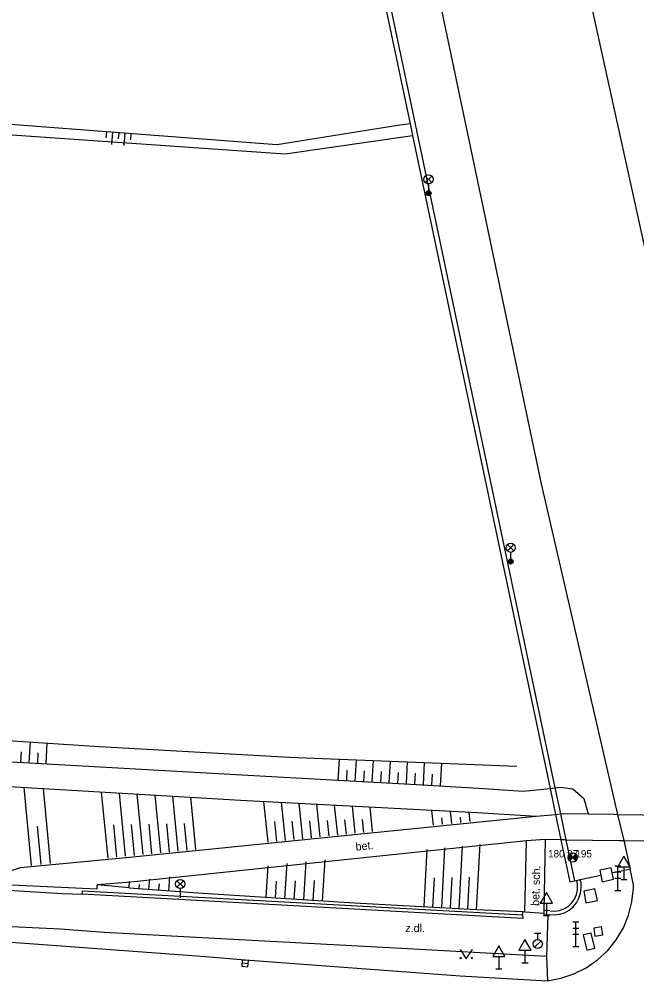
# Model space of a CAD drawing. Extents: x -538441 to -536770, y -1181008 to -1179809.
# Drawn here: x -537834.9 to -537784.8, y -1180620 to -1180541.9 of the extents above; entities that cross this region are included whole.
import ezdxf

# ---------------------------------------------------------------- set-up
doc = ezdxf.new("R2010")
doc.units = 0
for name, color, linetype in [('Vrstva 10', 7, 'Continuous'), ('Vrstva 11', 7, 'Continuous'), ('Vrstva 14', 7, 'Continuous'), ('Vrstva 15', 7, 'Continuous'), ('Vrstva 17', 7, 'Continuous'), ('Vrstva 18', 7, 'Continuous'), ('Vrstva 22', 7, 'Continuous'), ('Vrstva 27', 7, 'Continuous'), ('Vrstva 28', 7, 'Continuous'), ('Vrstva 33', 7, 'Continuous'), ('Vrstva 34', 7, 'Continuous'), ('Vrstva 36', 7, 'Continuous'), ('Vrstva 40', 7, 'Continuous'), ('Vrstva 7', 7, 'Continuous')]:
    doc.layers.add(name, color=color, linetype=linetype)

msp = doc.modelspace()

# ---------------------------------------------------------------- linework, layer by layer
at = {"layer": 'Vrstva 10'}
for p, q in [((-537782.938, -1180565.756), (-537790.569, -1180530.964)), ((-537800.99, -1180539.42), (-537792.522, -1180579.638)), ((-537836.53, -1180602.14), (-537816.83, -1180603.26)), ((-537836.67, -1180604.15), (-537816.94, -1180605.31)), ((-537802.65, -1180604.04), (-537797.61, -1180604.34)), ((-537816.94, -1180605.31), (-537797.68, -1180606.33)), ((-537789.05, -1180605.19), (-537788.695, -1180606.438)), ((-537797.68, -1180606.33), (-537792.93, -1180606.63)), ((-537785.02, -1180612.192), (-537785.28, -1180610.905)), ((-537791.83, -1180614.314), (-537792.294, -1180614.271)), ((-537845.022, -1180616.127), (-537830.791, -1180617.208)), ((-537830.791, -1180617.208), (-537819.78, -1180618.02)), ((-537819.78, -1180618.02), (-537816.56, -1180618.29)), ((-537816.56, -1180618.29), (-537799.11, -1180619.59)), ((-537799.11, -1180619.59), (-537792.017, -1180619.988))]:
    msp.add_line(p, q, dxfattribs=at)
for points in [[(-537792.522, -1180579.638), (-537786.307, -1180606.472)], [(-537816.83, -1180603.26), (-537809.009, -1180603.69)], [(-537809.009, -1180603.69), (-537802.65, -1180604.04)], [(-537797.61, -1180604.34), (-537793.99, -1180604.58), (-537791.8, -1180604.359), (-537791.4, -1180604.319), (-537790.92, -1180604.27), (-537789.96, -1180604.41), (-537789.05, -1180605.19)], [(-537786.307, -1180606.472), (-537785.814, -1180608.6), (-537785.28, -1180610.905)], [(-537791.878, -1180614.61), (-537791.454, -1180614.638), (-537791.033, -1180614.587), (-537790.629, -1180614.458), (-537790.256, -1180614.255), (-537789.927, -1180613.986), (-537789.655, -1180613.66), (-537789.449, -1180613.289), (-537789.315, -1180612.886), (-537789.26, -1180612.465), (-537789.284, -1180612.041), (-537789.341, -1180611.776)], [(-537791.83, -1180614.314), (-537791.435, -1180614.338), (-537791.044, -1180614.282), (-537790.672, -1180614.148), (-537790.334, -1180613.943), (-537790.045, -1180613.673), (-537789.816, -1180613.352), (-537789.655, -1180612.99), (-537789.571, -1180612.604), (-537789.566, -1180612.209), (-537789.633, -1180611.839)], [(-537790.198, -1180611.962), (-537789.807, -1180611.877), (-537789.633, -1180611.839), (-537789.341, -1180611.776)], [(-537785.418, -1180614.664), (-537785.143, -1180613.579), (-537785.025, -1180612.466), (-537785.02, -1180612.192)], [(-537792.017, -1180619.988), (-537790.916, -1180619.789), (-537789.854, -1180619.435), (-537788.854, -1180618.934), (-537787.935, -1180618.295), (-537787.117, -1180617.532), (-537786.415, -1180616.661), (-537785.845, -1180615.698), (-537785.418, -1180614.664)]]:
    msp.add_lwpolyline(points, dxfattribs=at)
at = {"layer": 'Vrstva 11'}
for p, q in [((-537826.23, -1180609.98), (-537792.93, -1180606.63)), ((-537792.93, -1180606.63), (-537791.354, -1180606.477)), ((-537793.7, -1180608.63), (-537825.85, -1180611.97)), ((-537793.843, -1180614.38), (-537793.7, -1180608.63)), ((-537790.512, -1180608.534), (-537790.922, -1180608.528)), ((-537834.82, -1180610.79), (-537826.23, -1180609.98)), ((-537789.341, -1180611.776), (-537787.667, -1180611.413)), ((-537786.822, -1180610.81), (-537787.75, -1180610.995)), ((-537786.742, -1180611.213), (-537785.28, -1180610.905)), ((-537828.62, -1180612.56), (-537837.76, -1180612.13)), ((-537787.56, -1180611.949), (-537786.636, -1180611.741)), ((-537837.92, -1180612.49), (-537831.44, -1180612.91)), ((-537831.44, -1180612.91), (-537829.81, -1180612.96)), ((-537829.81, -1180612.96), (-537829.79, -1180612.67)), ((-537794.01, -1180614.93), (-537829.81, -1180612.96)), ((-537788.15, -1180612.53), (-537789.055, -1180612.71)), ((-537789.055, -1180612.71), (-537788.879, -1180613.653)), ((-537787.934, -1180613.464), (-537788.15, -1180612.53)), ((-537788.879, -1180613.653), (-537787.934, -1180613.464)), ((-537794.03, -1180614.62), (-537794.01, -1180614.93)), ((-537791.99, -1180614.62), (-537792.08, -1180618.02)), ((-537831.6, -1180615.8), (-537838.11, -1180615.49)), ((-537828.03, -1180616.08), (-537831.6, -1180615.8)), ((-537818.06, -1180616.62), (-537828.03, -1180616.08)), ((-537787.616, -1180615.603), (-537788.251, -1180615.717)), ((-537788.251, -1180615.717), (-537788.167, -1180616.376)), ((-537787.499, -1180616.256), (-537787.616, -1180615.603)), ((-537804.84, -1180617.32), (-537818.06, -1180616.62)), ((-537788.458, -1180616.115), (-537789.102, -1180616.267)), ((-537789.102, -1180616.267), (-537788.811, -1180617.498)), ((-537788.169, -1180617.338), (-537788.458, -1180616.115)), ((-537788.167, -1180616.376), (-537787.499, -1180616.256)), ((-537792.08, -1180618.02), (-537804.84, -1180617.32)), ((-537788.811, -1180617.498), (-537788.169, -1180617.338)), ((-537792.08, -1180618.02), (-537792.017, -1180619.988))]:
    msp.add_line(p, q, dxfattribs=at)
for points in [[(-537791.354, -1180606.477), (-537790.954, -1180606.437), (-537790.68, -1180606.41)], [(-537790.68, -1180606.41), (-537788.695, -1180606.438), (-537786.648, -1180606.467), (-537786.307, -1180606.472)], [(-537786.307, -1180606.472), (-537773.969, -1180606.647)], [(-537790.922, -1180608.528), (-537792.19, -1180608.51), (-537793.7, -1180608.63)], [(-537792.19, -1180608.51), (-537792.294, -1180614.271)], [(-537790.512, -1180608.534), (-537786.182, -1180608.595), (-537785.814, -1180608.6)], [(-537785.814, -1180608.6), (-537773.502, -1180608.774)], [(-537837.76, -1180612.13), (-537837.76, -1180611.819), (-537837.76, -1180611.76), (-537834.82, -1180610.79)], [(-537787.75, -1180610.995), (-537787.667, -1180611.413), (-537787.56, -1180611.949)], [(-537786.636, -1180611.741), (-537786.742, -1180611.213), (-537786.822, -1180610.81)], [(-537825.85, -1180611.97), (-537828.6, -1180612.2), (-537828.603, -1180612.26), (-537828.62, -1180612.56)], [(-537829.79, -1180612.67), (-537794.03, -1180614.62)], [(-537794.03, -1180614.62), (-537793.98, -1180614.37), (-537793.843, -1180614.38), (-537792.3, -1180614.5)], [(-537792.294, -1180614.271), (-537792.296, -1180614.344), (-537792.3, -1180614.5), (-537792.301, -1180614.645)], [(-537792.301, -1180614.645), (-537791.99, -1180614.62), (-537791.878, -1180614.61)]]:
    msp.add_lwpolyline(points, dxfattribs=at)
at = {"layer": 'Vrstva 14'}
for p, q in [((-537813.99, -1180552.09), (-537845.5, -1180549.69)), ((-537804.01, -1180550.49), (-537813.99, -1180552.09)), ((-537803.174, -1180550.395), (-537804.01, -1180550.49)), ((-537844.5, -1180550.67), (-537813.33, -1180552.82)), ((-537813.33, -1180552.82), (-537802.975, -1180551.339)), ((-537842.206, -1180600.052), (-537828.424, -1180600.954)), ((-537828.424, -1180600.954), (-537812.97, -1180601.814)), ((-537812.97, -1180601.814), (-537808.912, -1180601.979)), ((-537809.009, -1180603.69), (-537808.912, -1180601.979)), ((-537808.912, -1180601.979), (-537794.501, -1180602.565)), ((-537825.992, -1180612.428), (-537828.6, -1180612.2)), ((-537825.992, -1180612.428), (-537820, -1180612.877)), ((-537820, -1180612.877), (-537807.695, -1180613.669)), ((-537807.695, -1180613.669), (-537797.761, -1180614.186)), ((-537797.761, -1180614.186), (-537793.98, -1180614.37))]:
    msp.add_line(p, q, dxfattribs=at)
at = {"layer": 'Vrstva 15'}
for p, q in [((-537827.838, -1180551.035), (-537827.876, -1180551.534)), ((-537827.34, -1180551.073), (-537827.416, -1180552.07)), ((-537826.841, -1180551.111), (-537826.879, -1180551.61)), ((-537826.342, -1180551.149), (-537826.418, -1180552.146)), ((-537825.844, -1180551.187), (-537825.882, -1180551.686)), ((-537834.099, -1180602.278), (-537833.997, -1180600.589)), ((-537832.74, -1180602.349), (-537832.639, -1180600.678)), ((-537834.778, -1180602.24), (-537834.727, -1180601.386)), ((-537833.419, -1180602.317), (-537833.368, -1180601.471)), ((-537807.625, -1180603.766), (-537807.527, -1180602.035)), ((-537806.242, -1180603.842), (-537806.142, -1180602.092)), ((-537804.858, -1180603.919), (-537804.757, -1180602.148)), ((-537803.473, -1180603.995), (-537803.372, -1180602.204)), ((-537802.089, -1180604.073), (-537801.987, -1180602.261)), ((-537800.707, -1180604.162), (-537800.602, -1180602.317)), ((-537808.317, -1180603.728), (-537808.268, -1180602.869)), ((-537806.933, -1180603.804), (-537806.884, -1180602.936)), ((-537805.55, -1180603.881), (-537805.499, -1180603.003)), ((-537804.165, -1180603.957), (-537804.115, -1180603.071)), ((-537802.781, -1180604.033), (-537802.731, -1180603.138)), ((-537801.399, -1180604.114), (-537801.346, -1180603.206)), ((-537833.925, -1180610.616), (-537834.53, -1180604.287)), ((-537832.377, -1180610.468), (-537832.958, -1180604.382)), ((-537827.708, -1180610.019), (-537828.225, -1180604.668)), ((-537826.282, -1180609.881), (-537826.777, -1180604.756)), ((-537824.855, -1180609.744), (-537825.329, -1180604.838)), ((-537823.429, -1180609.606), (-537823.882, -1180604.919)), ((-537822.002, -1180609.468), (-537822.434, -1180605.001)), ((-537820.576, -1180609.33), (-537820.986, -1180605.082)), ((-537814.704, -1180608.74), (-537815.048, -1180605.414)), ((-537813.289, -1180608.594), (-537813.61, -1180605.494)), ((-537811.875, -1180608.447), (-537812.173, -1180605.573)), ((-537810.461, -1180608.301), (-537810.735, -1180605.652)), ((-537809.046, -1180608.154), (-537809.297, -1180605.731)), ((-537807.632, -1180608.008), (-537807.859, -1180605.809)), ((-537806.217, -1180607.862), (-537806.422, -1180605.888)), ((-537801.278, -1180607.356), (-537801.399, -1180606.163)), ((-537799.785, -1180607.206), (-537799.881, -1180606.246)), ((-537799.038, -1180607.13), (-537799.081, -1180606.709)), ((-537798.291, -1180607.055), (-537798.364, -1180606.329)), ((-537833.151, -1180610.542), (-537833.448, -1180607.438)), ((-537826.995, -1180609.95), (-537827.248, -1180607.331)), ((-537825.568, -1180609.812), (-537825.811, -1180607.305)), ((-537824.142, -1180609.675), (-537824.374, -1180607.277)), ((-537822.716, -1180609.537), (-537822.937, -1180607.248)), ((-537821.289, -1180609.399), (-537821.5, -1180607.22)), ((-537813.997, -1180608.667), (-537814.163, -1180607.061)), ((-537812.582, -1180608.521), (-537812.737, -1180607.027)), ((-537811.168, -1180608.374), (-537811.311, -1180606.993)), ((-537809.753, -1180608.228), (-537809.885, -1180606.96)), ((-537808.339, -1180608.081), (-537808.459, -1180606.926)), ((-537806.924, -1180607.935), (-537807.032, -1180606.892)), ((-537800.532, -1180607.281), (-537800.586, -1180606.743)), ((-537799.181, -1180614.112), (-537798.917, -1180609.047)), ((-537797.761, -1180614.186), (-537797.486, -1180608.904)), ((-537802.021, -1180613.965), (-537801.779, -1180609.333)), ((-537800.601, -1180614.039), (-537800.348, -1180609.19)), ((-537813.336, -1180613.306), (-537813.154, -1180610.471)), ((-537811.81, -1180613.404), (-537811.612, -1180610.315)), ((-537810.285, -1180613.502), (-537810.07, -1180610.161)), ((-537814.862, -1180613.208), (-537814.697, -1180610.646)), ((-537825.992, -1180612.428), (-537825.954, -1180611.924)), ((-537825.185, -1180612.489), (-537825.16, -1180612.16)), ((-537824.378, -1180612.549), (-537824.317, -1180611.738)), ((-537823.571, -1180612.61), (-537823.534, -1180612.127)), ((-537822.763, -1180612.67), (-537822.68, -1180611.552)), ((-537814.099, -1180613.257), (-537814.012, -1180611.908)), ((-537812.573, -1180613.355), (-537812.478, -1180611.874)), ((-537811.048, -1180613.453), (-537810.944, -1180611.846)), ((-537801.311, -1180614.002), (-537801.187, -1180611.632)), ((-537799.891, -1180614.076), (-537799.762, -1180611.597)), ((-537798.471, -1180614.149), (-537798.336, -1180611.563))]:
    msp.add_line(p, q, dxfattribs=at)
at = {"layer": 'Vrstva 17'}
for p, q in [((-537790.334, -1180609.991), (-537790.137, -1180609.793)), ((-537790.331, -1180609.917), (-537790.172, -1180609.758)), ((-537790.326, -1180610.053), (-537790.101, -1180609.829)), ((-537790.303, -1180609.818), (-537790.207, -1180609.723)), ((-537790.225, -1180610.235), (-537789.695, -1180609.705)), ((-537790.225, -1180609.705), (-537789.695, -1180610.235)), ((-537789.925, -1180610.005), (-537789.662, -1180609.743)), ((-537789.889, -1180610.041), (-537789.634, -1180609.785)), ((-537789.854, -1180610.076), (-537789.611, -1180609.833)), ((-537790.309, -1180610.107), (-537790.066, -1180609.864)), ((-537790.286, -1180610.155), (-537790.031, -1180609.899)), ((-537790.258, -1180610.197), (-537789.995, -1180609.935)), ((-537789.819, -1180610.111), (-537789.594, -1180609.887)), ((-537789.783, -1180610.147), (-537789.586, -1180609.949)), ((-537789.748, -1180610.182), (-537789.589, -1180610.023)), ((-537789.713, -1180610.217), (-537789.617, -1180610.122))]:
    msp.add_line(p, q, dxfattribs=at)
msp.add_circle((-537789.96, -1180609.97), 0.375, dxfattribs=at)
at = {"layer": 'Vrstva 27'}
msp.add_line((-537816.32, -1180618.604), (-537816.818, -1180618.566), dxfattribs=at)
msp.add_lwpolyline([(-537816.301, -1180618.355), (-537816.799, -1180618.317), (-537816.837, -1180618.815), (-537816.339, -1180618.853)], close=True, dxfattribs=at)
at = {"layer": 'Vrstva 28'}
for p, q in [((-537793.058, -1180617.272), (-537792.528, -1180616.742)), ((-537793.05, -1180616.125), (-537792.55, -1180616.125)), ((-537792.8, -1180616.625), (-537792.8, -1180616.125))]:
    msp.add_line(p, q, dxfattribs=at)
msp.add_circle((-537792.8, -1180617), 0.375, dxfattribs=at)
at = {"layer": 'Vrstva 33'}
for p, q in [((-537801.935, -1180555.16), (-537801.405, -1180554.63)), ((-537801.935, -1180554.63), (-537801.405, -1180555.16)), ((-537801.67, -1180555.27), (-537801.67, -1180556.02)), ((-537795.264, -1180585.081), (-537794.736, -1180584.551)), ((-537795.264, -1180584.551), (-537794.736, -1180585.081)), ((-537795, -1180585.19), (-537795, -1180585.94)), ((-537786.54, -1180610.651), (-537786.04, -1180610.651)), ((-537786.54, -1180611.151), (-537786.04, -1180611.151)), ((-537786.29, -1180612.651), (-537786.29, -1180610.651)), ((-537822.105, -1180612.39), (-537821.575, -1180611.86)), ((-537822.105, -1180611.86), (-537821.575, -1180612.39)), ((-537786.54, -1180611.651), (-537786.04, -1180611.651)), ((-537821.84, -1180612.5), (-537821.84, -1180613.25)), ((-537786.54, -1180612.651), (-537786.04, -1180612.651)), ((-537789.952, -1180615.208), (-537789.452, -1180615.208)), ((-537789.702, -1180617.208), (-537789.702, -1180615.208)), ((-537789.952, -1180615.708), (-537789.452, -1180615.708)), ((-537789.952, -1180616.208), (-537789.452, -1180616.208)), ((-537789.952, -1180617.208), (-537789.452, -1180617.208))]:
    msp.add_line(p, q, dxfattribs=at)
for centre, radius in [((-537801.67, -1180554.895), 0.375), ((-537801.67, -1180556.02), 0.2), ((-537801.67, -1180556.02), 0.145), ((-537801.67, -1180556.02), 0.0876), ((-537795, -1180584.816), 0.375), ((-537795, -1180585.941), 0.2), ((-537795, -1180585.941), 0.145), ((-537795, -1180585.941), 0.0876), ((-537821.84, -1180612.125), 0.375)]:
    msp.add_circle(centre, radius, dxfattribs=at)
at = {"layer": 'Vrstva 34'}
for p, q in [((-537785.803, -1180610.734), (-537785.803, -1180611.752)), ((-537786.053, -1180611.752), (-537785.553, -1180611.752)), ((-537792.09, -1180613.672), (-537792.09, -1180614.69)), ((-537792.34, -1180614.69), (-537791.84, -1180614.69)), ((-537793.84, -1180617.502), (-537793.84, -1180618.52)), ((-537795.959, -1180618.004), (-537795.959, -1180619.022)), ((-537796.209, -1180619.022), (-537795.709, -1180619.022)), ((-537794.09, -1180618.52), (-537793.59, -1180618.52))]:
    msp.add_line(p, q, dxfattribs=at)
for points in [[(-537786.303, -1180610.734), (-537785.303, -1180610.734), (-537785.803, -1180609.868)], [(-537792.59, -1180613.672), (-537791.59, -1180613.672), (-537792.09, -1180612.806)], [(-537794.34, -1180617.502), (-537793.34, -1180617.502), (-537793.84, -1180616.636)], [(-537796.459, -1180618.004), (-537795.459, -1180618.004), (-537795.959, -1180617.138)]]:
    msp.add_lwpolyline(points, close=True, dxfattribs=at)
at = {"layer": 'Vrstva 36'}
msp.add_lwpolyline([(-537799.104, -1180617.452), (-537798.604, -1180618.202), (-537798.104, -1180617.452)], dxfattribs=at)
for centre in [(-537799.054, -1180618.152), (-537798.155, -1180618.152)]:
    msp.add_circle(centre, 0.05, dxfattribs=at)
at = {"layer": 'Vrstva 7'}
for p, q in [((-537805.48, -1180539.457), (-537803.174, -1180550.395)), ((-537805.09, -1180539.37), (-537791.4, -1180604.319)), ((-537803.174, -1180550.395), (-537802.975, -1180551.339)), ((-537802.975, -1180551.339), (-537791.8, -1180604.359))]:
    msp.add_line(p, q, dxfattribs=at)
for points in [[(-537791.8, -1180604.359), (-537791.354, -1180606.477), (-537790.922, -1180608.528), (-537790.198, -1180611.962)], [(-537791.4, -1180604.319), (-537790.954, -1180606.437), (-537790.512, -1180608.534), (-537789.807, -1180611.877)]]:
    msp.add_lwpolyline(points, dxfattribs=at)

# ---------------------------------------------------------------- texts
at = {"layer": 'Vrstva 18'}
msp.add_text(' 195', height=0.6, dxfattribs=at).set_placement((-537789.96, -1180609.97))
at = {"layer": 'Vrstva 22'}
msp.add_text('180 97 ', height=0.6, dxfattribs=at).set_placement((-537791.96, -1180609.97))
at = {"layer": 'Vrstva 40'}
for s, rotation, p in [('bet.', 5.93107, (-537807.567, -1180609.43)), ('bet. sch.', 88.48239, (-537792.681, -1180613.915))]:
    msp.add_text(s, height=0.65, rotation=rotation, dxfattribs=at).set_placement(p)
msp.add_text('z.dl.', height=0.65, dxfattribs=at).set_placement((-537803.558, -1180616.039))

doc.saveas('drawing.dxf')
